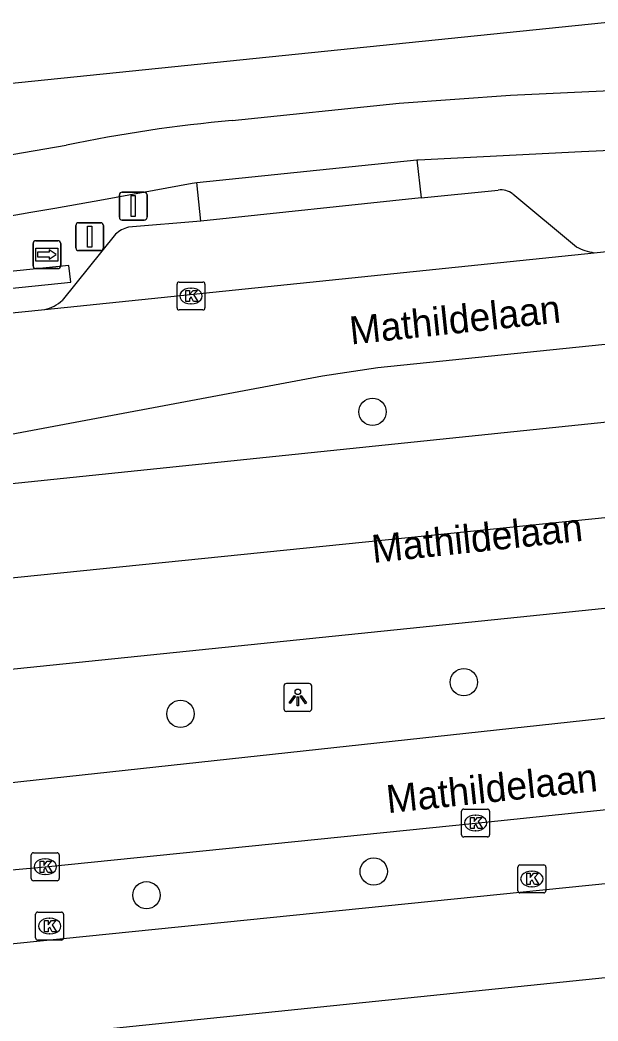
# Model space of a CAD drawing. Extents: x 160676 to 161153, y 383244 to 383713.
# Drawn here: x 161054.61 to 161075.29, y 383550.95 to 383586.79 of the extents above; entities that cross this region are included whole.
import ezdxf

# ---------------------------------------------------------------- set-up
doc = ezdxf.new("R2010")
doc.units = 0
for name, color, linetype in [('IMGEO_Afsluitpaal', 7, 'Continuous'), ('IMGEO_Boom', 7, 'Continuous'), ('IMGEO_Fietspad_gesloten', 7, 'Continuous'), ('IMGEO_Haag', 7, 'Continuous'), ('IMGEO_Kolk', 7, 'Continuous'), ('IMGEO_Lichtpunt', 7, 'Continuous'), ('IMGEO_Openbare_ruimte_label', 7, 'Continuous'), ('IMGEO_OVBaan_gesloten', 7, 'Continuous'), ('IMGEO_Pand', 7, 'Continuous'), ('IMGEO_Parkeervlak_open', 7, 'Continuous'), ('IMGEO_Rijbaan_lokaal_gesloten', 7, 'Continuous'), ('IMGEO_Voetpad_open', 7, 'Continuous'), ('IMGEO_Wegwijzer', 7, 'Continuous')]:
    doc.layers.add(name, color=color, linetype=linetype)

msp = doc.modelspace()

# ---------------------------------------------------------------- linework, layer by layer
at = {"layer": 'IMGEO_Afsluitpaal'}
for p, q in [((161058.161, 383579.726), (161058.161, 383580.526)), ((161058.161, 383580.526), (161058.161, 383579.726)), ((161058.261, 383580.626), (161059.051, 383580.626)), ((161059.051, 383580.626), (161058.261, 383580.626)), ((161059.151, 383580.526), (161059.151, 383579.726)), ((161059.151, 383579.726), (161059.151, 383580.526)), ((161059.051, 383579.626), (161058.261, 383579.626)), ((161058.261, 383579.626), (161059.051, 383579.626)), ((161056.603, 383578.633), (161056.603, 383579.433)), ((161056.603, 383579.433), (161056.603, 383578.633)), ((161056.703, 383579.533), (161057.493, 383579.533)), ((161057.493, 383579.533), (161056.703, 383579.533)), ((161057.593, 383579.433), (161057.593, 383578.633)), ((161057.593, 383578.633), (161057.593, 383579.433)), ((161057.493, 383578.533), (161056.703, 383578.533)), ((161056.703, 383578.533), (161057.493, 383578.533))]:
    msp.add_line(p, q, dxfattribs=at)
for points in [[(161058.581, 383580.501), (161058.731, 383580.501), (161058.731, 383579.751), (161058.581, 383579.751), (161058.581, 383580.501)], [(161057.023, 383579.408), (161057.173, 383579.408), (161057.173, 383578.658), (161057.023, 383578.658), (161057.023, 383579.408)]]:
    msp.add_lwpolyline(points, dxfattribs=at)
for centre, start, end in [((161058.261, 383580.526), 90, 180), ((161058.261, 383580.526), 90, 180), ((161059.051, 383580.526), 0, 90), ((161059.051, 383580.526), 360, 90), ((161058.261, 383579.726), 180, 270), ((161058.261, 383579.726), 180, 270), ((161059.051, 383579.726), 270, 0), ((161059.051, 383579.726), 270, 0), ((161056.703, 383579.433), 90, 180), ((161056.703, 383579.433), 90, 180), ((161057.493, 383579.433), 0, 90), ((161057.493, 383579.433), 360, 90), ((161056.703, 383578.633), 180, 270), ((161056.703, 383578.633), 180, 270), ((161057.493, 383578.633), 270, 0), ((161057.493, 383578.633), 270, 0)]:
    msp.add_arc(centre, 0.1, start, end, dxfattribs=at)
at = {"layer": 'IMGEO_Boom'}
for centre in [(161067.224, 383572.759), (161070.49, 383563.086), (161060.349, 383561.947), (161067.266, 383556.306), (161059.135, 383555.455)]:
    msp.add_circle(centre, 0.489, dxfattribs=at)
at = {"layer": 'IMGEO_Fietspad_gesloten'}
for points in [[(161062.195, 383583.186), (161068.177, 383583.808), (161072.168, 383584.096), (161084.155, 383584.661), (161085.622, 383584.741)], [(161068.814, 383581.779), (161068.858, 383581.784), (161074.699, 383582.085), (161084.836, 383582.551)], [(161000.877, 383575.549), (161009.712, 383576.451), (161032.513, 383578.778), (161034.486, 383579.01), (161049.373, 383581.126), (161056.263, 383582.305)], [(161060.938, 383580.969), (161068.814, 383581.779)], [(161057.592, 383580.363), (161060.766, 383580.951), (161060.938, 383580.969)], [(161053.666, 383553.653), (161130.013, 383561.398)], [(161030.95, 383547.693), (161037.578, 383548.506), (161047.631, 383549.64), (161127.202, 383557.831)]]:
    msp.add_lwpolyline(points, dxfattribs=at)
for centre, radius, start, end in [((161066.606, 383533.077), 50.303, 95.0302, 101.865), ((160983.214, 383998.386), 424.589, 276.28566, 280.08898)]:
    msp.add_arc(centre, radius, start, end, dxfattribs=at)
at = {"layer": 'IMGEO_Haag'}
msp.add_lwpolyline([(161056.42, 383577.406), (161056.389, 383577.704), (161056.358, 383578.002), (161013.777, 383573.636), (161013.808, 383573.338), (161013.839, 383573.04), (161056.42, 383577.406)], dxfattribs=at)
at = {"layer": 'IMGEO_Kolk'}
for p, q in [((161060.225, 383576.483), (161060.225, 383577.335)), ((161060.3, 383577.409), (161061.152, 383577.409)), ((161060.713, 383577.189), (161060.738, 383577.189)), ((161061.226, 383577.335), (161061.226, 383576.483)), ((161061.152, 383576.409), (161060.3, 383576.409)), ((161060.736, 383576.629), (161060.711, 383576.629)), ((161070.412, 383557.615), (161070.412, 383558.467)), ((161070.487, 383558.541), (161071.339, 383558.541)), ((161071.413, 383558.467), (161071.413, 383557.615)), ((161070.9, 383558.321), (161070.925, 383558.321)), ((161070.923, 383557.761), (161070.898, 383557.761)), ((161071.339, 383557.541), (161070.487, 383557.541)), ((161055.009, 383556.049), (161055.009, 383556.901)), ((161055.084, 383556.975), (161055.936, 383556.975)), ((161055.497, 383556.755), (161055.522, 383556.755)), ((161056.01, 383556.901), (161056.01, 383556.049)), ((161072.426, 383555.614), (161072.426, 383556.466)), ((161072.501, 383556.54), (161073.353, 383556.54)), ((161072.914, 383556.32), (161072.939, 383556.32)), ((161073.427, 383556.466), (161073.427, 383555.614)), ((161055.936, 383555.975), (161055.084, 383555.975)), ((161055.52, 383556.195), (161055.495, 383556.195)), ((161072.937, 383555.76), (161072.912, 383555.76)), ((161073.353, 383555.54), (161072.501, 383555.54)), ((161055.164, 383553.925), (161055.164, 383554.777)), ((161055.239, 383554.851), (161056.091, 383554.851)), ((161055.652, 383554.631), (161055.677, 383554.631)), ((161056.165, 383554.777), (161056.165, 383553.925)), ((161056.091, 383553.851), (161055.239, 383553.851)), ((161055.675, 383554.071), (161055.65, 383554.071))]:
    msp.add_line(p, q, dxfattribs=at)
for points in [[(161060.225, 383576.483), (161060.225, 383577.335)], [(161060.3, 383577.409), (161061.152, 383577.409)], [(161060.546, 383577.109), (161060.669, 383577.109), (161060.669, 383576.958), (161060.799, 383577.109), (161060.963, 383577.109), (161060.817, 383576.958), (161060.97, 383576.709), (161060.818, 383576.709), (161060.733, 383576.873), (161060.669, 383576.806), (161060.669, 383576.709), (161060.546, 383576.709), (161060.546, 383577.109)], [(161061.226, 383577.335), (161061.226, 383576.483)], [(161061.152, 383576.409), (161060.3, 383576.409)], [(161070.412, 383557.615), (161070.412, 383558.467)], [(161070.487, 383558.541), (161071.339, 383558.541)], [(161071.413, 383558.467), (161071.413, 383557.615)], [(161070.733, 383558.241), (161070.856, 383558.241), (161070.856, 383558.09), (161070.986, 383558.241), (161071.15, 383558.241), (161071.004, 383558.09), (161071.157, 383557.841), (161071.005, 383557.841), (161070.92, 383558.005), (161070.856, 383557.938), (161070.856, 383557.841), (161070.733, 383557.841), (161070.733, 383558.241)], [(161071.339, 383557.541), (161070.487, 383557.541)], [(161055.009, 383556.049), (161055.009, 383556.901)], [(161055.084, 383556.975), (161055.936, 383556.975)], [(161055.33, 383556.675), (161055.453, 383556.675), (161055.453, 383556.524), (161055.583, 383556.675), (161055.747, 383556.675), (161055.601, 383556.524), (161055.754, 383556.275), (161055.602, 383556.275), (161055.517, 383556.439), (161055.453, 383556.372), (161055.453, 383556.275), (161055.33, 383556.275), (161055.33, 383556.675)], [(161056.01, 383556.901), (161056.01, 383556.049)], [(161072.426, 383555.614), (161072.426, 383556.466)], [(161072.501, 383556.54), (161073.353, 383556.54)], [(161073.427, 383556.466), (161073.427, 383555.614)], [(161055.936, 383555.975), (161055.084, 383555.975)], [(161072.747, 383556.24), (161072.87, 383556.24), (161072.87, 383556.089), (161073, 383556.24), (161073.164, 383556.24), (161073.018, 383556.089), (161073.171, 383555.84), (161073.019, 383555.84), (161072.934, 383556.004), (161072.87, 383555.937), (161072.87, 383555.84), (161072.747, 383555.84), (161072.747, 383556.24)], [(161073.353, 383555.54), (161072.501, 383555.54)], [(161055.164, 383553.925), (161055.164, 383554.777)], [(161055.239, 383554.851), (161056.091, 383554.851)], [(161055.485, 383554.551), (161055.608, 383554.551), (161055.608, 383554.4), (161055.738, 383554.551), (161055.902, 383554.551), (161055.756, 383554.4), (161055.909, 383554.151), (161055.757, 383554.151), (161055.672, 383554.315), (161055.608, 383554.248), (161055.608, 383554.151), (161055.485, 383554.151), (161055.485, 383554.551)], [(161056.165, 383554.777), (161056.165, 383553.925)], [(161056.091, 383553.851), (161055.239, 383553.851)]]:
    msp.add_lwpolyline(points, dxfattribs=at)
for centre, start, end in [((161060.302, 383577.333), 91.552, 178.448), ((161060.302, 383577.333), 91.552, 178.448), ((161061.15, 383577.333), 1.552, 88.448), ((161061.15, 383577.333), 1.552, 88.448), ((161060.302, 383576.485), 181.552, 268.448), ((161060.302, 383576.485), 181.552, 268.448), ((161061.15, 383576.485), 271.552, 358.448), ((161061.15, 383576.485), 271.552, 358.448), ((161070.489, 383558.465), 91.552, 178.448), ((161070.489, 383558.465), 91.552, 178.448), ((161071.337, 383558.465), 1.552, 88.448), ((161071.337, 383558.465), 1.552, 88.448), ((161070.489, 383557.617), 181.552, 268.448), ((161070.489, 383557.617), 181.552, 268.448), ((161071.337, 383557.617), 271.552, 358.448), ((161071.337, 383557.617), 271.552, 358.448), ((161055.086, 383556.899), 91.552, 178.448), ((161055.086, 383556.899), 91.552, 178.448), ((161055.934, 383556.899), 1.552, 88.448), ((161055.934, 383556.899), 1.552, 88.448), ((161072.503, 383556.464), 91.552, 178.448), ((161072.503, 383556.464), 91.552, 178.448), ((161073.351, 383556.464), 1.552, 88.448), ((161073.351, 383556.464), 1.552, 88.448), ((161055.086, 383556.051), 181.552, 268.448), ((161055.086, 383556.051), 181.552, 268.448), ((161055.934, 383556.051), 271.552, 358.448), ((161055.934, 383556.051), 271.552, 358.448), ((161072.503, 383555.616), 181.552, 268.448), ((161072.503, 383555.616), 181.552, 268.448), ((161073.351, 383555.616), 271.552, 358.448), ((161073.351, 383555.616), 271.552, 358.448), ((161055.241, 383554.775), 91.552, 178.448), ((161055.241, 383554.775), 91.552, 178.448), ((161056.089, 383554.775), 1.552, 88.448), ((161056.089, 383554.775), 1.552, 88.448), ((161055.241, 383553.927), 181.552, 268.448), ((161055.241, 383553.927), 181.552, 268.448), ((161056.089, 383553.927), 271.552, 358.448), ((161056.089, 383553.927), 271.552, 358.448)]:
    msp.add_arc(centre, 0.0765, start, end, dxfattribs=at)
for centre, major_axis, ratio, start_param, end_param in [((161060.712, 383576.909), (-0.387, 0.002), 0.722429, 4.712389, 7.853982), ((161060.737, 383576.909), (-0.39, 0.002), 0.717154, 1.570796, 4.712389), ((161070.899, 383558.041), (-0.387, 0.002), 0.722429, 4.712389, 7.853982), ((161070.924, 383558.041), (-0.39, 0.002), 0.717154, 1.570796, 4.712389), ((161055.496, 383556.475), (-0.387, 0.002), 0.722429, 4.712389, 7.853982), ((161055.521, 383556.475), (-0.39, 0.002), 0.717154, 1.570796, 4.712389), ((161072.913, 383556.04), (-0.387, 0.002), 0.722429, 4.712389, 7.853982), ((161072.938, 383556.04), (-0.39, 0.002), 0.717154, 1.570796, 4.712389), ((161055.651, 383554.351), (-0.387, 0.002), 0.722429, 4.712389, 7.853982), ((161055.676, 383554.351), (-0.39, 0.002), 0.717154, 1.570796, 4.712389)]:
    msp.add_ellipse(centre, major_axis=major_axis, ratio=ratio, start_param=start_param, end_param=end_param, dxfattribs=at)
at = {"layer": 'IMGEO_Lichtpunt'}
for p, q in [((161064.051, 383562.941), (161064.051, 383562.134)), ((161064.051, 383562.941), (161064.051, 383562.134)), ((161064.953, 383563.036), (161064.145, 383563.036)), ((161064.953, 383563.036), (161064.145, 383563.036)), ((161065.047, 383562.134), (161065.047, 383562.941)), ((161065.047, 383562.134), (161065.047, 383562.941)), ((161064.145, 383562.04), (161064.953, 383562.04)), ((161064.145, 383562.04), (161064.953, 383562.04))]:
    msp.add_line(p, q, dxfattribs=at)
for points in [[(161064.425, 383562.605), (161064.464, 383562.577), (161064.276, 383562.315), (161064.238, 383562.342), (161064.425, 383562.605)], [(161064.527, 383562.557), (161064.574, 383562.557), (161064.574, 383562.235), (161064.527, 383562.235), (161064.527, 383562.557)], [(161064.637, 383562.577), (161064.675, 383562.604), (161064.862, 383562.342), (161064.823, 383562.314), (161064.637, 383562.577)]]:
    msp.add_lwpolyline(points, dxfattribs=at)
msp.add_circle((161064.55, 383562.739), 0.0994, dxfattribs=at)
for centre, start, end in [((161064.145, 383562.941), 90, 180), ((161064.145, 383562.941), 90, 180), ((161064.953, 383562.941), 0, 90), ((161064.953, 383562.941), 0, 90), ((161064.145, 383562.134), 180, 270), ((161064.145, 383562.134), 180, 270), ((161064.953, 383562.134), 270, 0), ((161064.953, 383562.134), 270, 360)]:
    msp.add_arc(centre, 0.0946, start, end, dxfattribs=at)
at = {"layer": 'IMGEO_OVBaan_gesloten'}
for points in [[(161128.738, 383574.467), (161099.72, 383571.421), (161045.124, 383565.881), (161015.167, 383562.758)], [(161015.019, 383566.144), (161038.417, 383568.551), (161084.138, 383573.282)], [(161015.36, 383559.547), (161128.627, 383571.185)]]:
    msp.add_lwpolyline(points, dxfattribs=at)
at = {"layer": 'IMGEO_Pand'}
msp.add_lwpolyline([(161076.456, 383586.789), (161027.74, 383581.8)], dxfattribs=at)
at = {"layer": 'IMGEO_Parkeervlak_open'}
for points in [[(161068.959, 383580.428), (161071.725, 383580.703)], [(161072.24, 383580.562), (161074.519, 383578.674)], [(161061.08, 383579.583), (161058.487, 383579.368)], [(161058.025, 383579.118), (161056.12, 383576.752)]]:
    msp.add_lwpolyline(points, dxfattribs=at)
for centre, radius, start, end in [((161071.809, 383580), 0.708, 52.5515, 96.8253), ((161058.724, 383578.377), 1.019, 103.4784, 133.3595), ((161075.378, 383580.179), 1.733, 240.274, 262.6948), ((161055.156, 383577.836), 1.45, 283.2171, 311.6404)]:
    msp.add_arc(centre, radius, start, end, dxfattribs=at)
at = {"layer": 'IMGEO_Rijbaan_lokaal_gesloten'}
for points in [[(161075.158, 383578.46), (161078.421, 383578.799), (161094.799, 383580.465), (161109.18, 383581.972), (161118.029, 383582.893)], [(161055.488, 383576.424), (161075.158, 383578.46)], [(161014.164, 383572.163), (161017.538, 383572.511), (161031.914, 383573.995), (161046.311, 383575.497), (161055.488, 383576.424)], [(161083.912, 383576.034), (161067.416, 383574.334), (161065.429, 383574.038), (161038.862, 383569.063)], [(161129.447, 383567.638), (161040.346, 383557.963), (161015.911, 383554.341)], [(161053.368, 383556.276), (161055.51, 383556.475), (161070.913, 383558.041), (161089.308, 383559.955), (161106.689, 383561.735), (161127.623, 383563.879), (161129.727, 383564.069)]]:
    msp.add_lwpolyline(points, dxfattribs=at)
at = {"layer": 'IMGEO_Voetpad_open'}
for points in [[(161068.814, 383581.779), (161068.959, 383580.428)], [(161061.08, 383579.583), (161060.938, 383580.969)], [(161068.959, 383580.428), (161061.08, 383579.583)]]:
    msp.add_lwpolyline(points, dxfattribs=at)
at = {"layer": 'IMGEO_Wegwijzer'}
for p, q in [((161055.171, 383578.889), (161055.961, 383578.889)), ((161055.961, 383578.889), (161055.171, 383578.889)), ((161055.071, 383577.989), (161055.071, 383578.789)), ((161055.071, 383578.789), (161055.071, 383577.989)), ((161056.061, 383578.789), (161056.061, 383577.989)), ((161056.061, 383577.989), (161056.061, 383578.789)), ((161055.961, 383577.889), (161055.171, 383577.889)), ((161055.171, 383577.889), (161055.961, 383577.889))]:
    msp.add_line(p, q, dxfattribs=at)
for points in [[(161055.172, 383578.621), (161055.96, 383578.621), (161055.96, 383578.157), (161055.172, 383578.157), (161055.172, 383578.621)], [(161055.237, 383578.473), (161055.237, 383578.389), (161055.237, 383578.305), (161055.648, 383578.305), (161055.648, 383578.222), (161055.895, 383578.389), (161055.648, 383578.556), (161055.648, 383578.473), (161055.237, 383578.473)]]:
    msp.add_lwpolyline(points, dxfattribs=at)
for centre, start, end in [((161055.171, 383578.789), 90, 180), ((161055.171, 383578.789), 90, 180), ((161055.961, 383578.789), 0, 90), ((161055.961, 383578.789), 360, 90), ((161055.171, 383577.989), 180, 270), ((161055.171, 383577.989), 180, 270), ((161055.961, 383577.989), 270, 0), ((161055.961, 383577.989), 270, 0)]:
    msp.add_arc(centre, 0.1, start, end, dxfattribs=at)

# ---------------------------------------------------------------- texts
at = {"layer": 'IMGEO_Openbare_ruimte_label'}
for p in [(161066.454, 383575.169), (161067.246, 383567.35), (161067.772, 383558.391)]:
    msp.add_text('Mathildelaan', height=1, rotation=6.024, dxfattribs=at).set_placement(p)

doc.saveas('drawing.dxf')
